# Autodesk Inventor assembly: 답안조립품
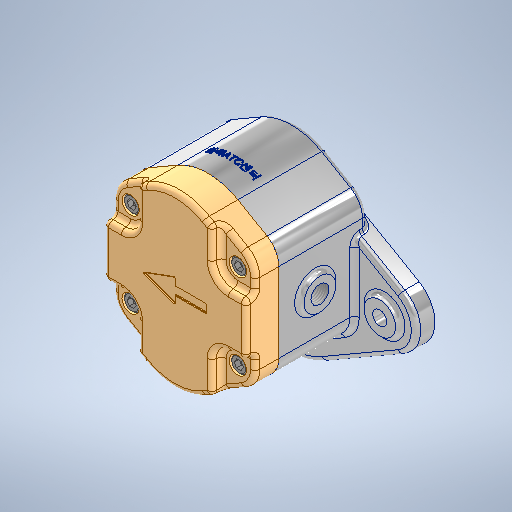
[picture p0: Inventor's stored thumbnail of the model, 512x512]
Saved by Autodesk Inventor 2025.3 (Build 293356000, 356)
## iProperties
Created: 2025-11
Part Number: 답안조립품
Document SubType Name: Assembly
Designer: PC-04
Author: PC-04
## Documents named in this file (11)
- C:\Users\PC-04\Desktop\751103V1010\답안조립품.iam
- C:\Users\PC-04\Desktop\751103V1010\본체.ipt
- C:\Users\PC-04\Desktop\751103V1010\6각 구멍붙이 볼트 M6x16\6각 구멍붙이 볼트 M6x16\6각 구멍붙이 볼트 M6x16.ipt
- C:\Users\PC-04\Desktop\751103V1010\실링\실링\실링.ipt
- C:\Users\PC-04\Desktop\751103V1010\커버\커버\커버.ipt
- C:\Users\PC-04\Desktop\751103V1010\3자 실링\3자 실링\3자 실링.ipt
- C:\Users\PC-04\Desktop\751103V1010\가이드 블록\가이드 블록\가이드 블록.ipt
- C:\Users\PC-04\Desktop\751103V1010\오일 실 16 30 7\오일 실 16 30 7\오일 실 16 30 7.ipt
- C:\Users\PC-04\Desktop\751103V1010\구동기어\구동기어\구동기어.ipt
- C:\Users\PC-04\Desktop\751103V1010\스퍼기어\스퍼기어\스퍼기어.ipt
- C:\Users\PC-04\Desktop\751103V1010\DU 부시\DU 부시\DU 부시.ipt
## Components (11 placed, 5 different names)
1. 6각 구멍붙이 볼트 M6x16:1
2. 6각 구멍붙이 볼트 M6x16:2
3. 6각 구멍붙이 볼트 M6x16:3
4. 6각 구멍붙이 볼트 M6x16:4
5. 3자 실링:1
6. 가이드 블록:1
7. 구동기어:1
8. DU 부시:1
9. DU 부시:2
10. DU 부시:3
11. DU 부시:4
